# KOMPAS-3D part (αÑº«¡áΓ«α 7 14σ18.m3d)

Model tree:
1. Эскиз:1
2. Операция выдавливания:1
     Толщина стенки 1 = 2; Толщина стенки 2 = 8; Расстояние 1 = 1
3. Эскиз:3
4. Операция выдавливания:2
     Толщина стенки 1 = 2; Толщина стенки 2 = 6; Расстояние 1 = 5
5. Эскиз:4
6. Операция выдавливания:3
     Толщина стенки 1 = 2; Толщина стенки 2 = 6; Расстояние 1 = 1
7. Эскиз:5
8. Эскиз:6
9. Операция выдавливания:4
     Толщина стенки 1 = 2; Толщина стенки 2 = 2.5; Расстояние 1 = 50
10. Эскиз:7
11. Вырезать элемент выдавливания:1
     Толщина стенки 2 = 1.5; Расстояние 1 = 40
12. Эскиз:8
13. Операция выдавливания:5
     Толщина стенки 1 = 2; Толщина стенки 2 = 2.5; Расстояние 1 = 50
14. Эскиз:9
15. Вырезать элемент выдавливания:2
     Толщина стенки 2 = 1.5; Расстояние 1 = 40
16. Эскиз:10
17. Операция выдавливания:6
     Толщина стенки 1 = 2; Толщина стенки 2 = 2.5; Расстояние 1 = 10
18. Эскиз:11
19. Операция выдавливания:7
     Толщина стенки 1 = 2; Толщина стенки 2 = 6; Расстояние 1 = 1
20. Эскиз:12
21. Операция выдавливания:8
     Толщина стенки 1 = 2; Толщина стенки 2 = 6; Расстояние 1 = 5
22. Эскиз:13
23. Операция выдавливания:9
     Толщина стенки 1 = 2; Толщина стенки 2 = 8; Расстояние 1 = 1
24. Эскиз:14
25. Вырезать элемент выдавливания:3
     Толщина стенки 2 = 1.5; Расстояние 1 = 23
26. Эскиз:15
27. Вырезать элемент выдавливания:4
     Толщина стенки 2 = 1.5; Расстояние 1 = 1
28. Эскиз:16
29. Вырезать элемент выдавливания:5
     Расстояние 1 = 150
30. Эскиз:21
31. Вырезать элемент выдавливания:6
     Расстояние 1 = 20
